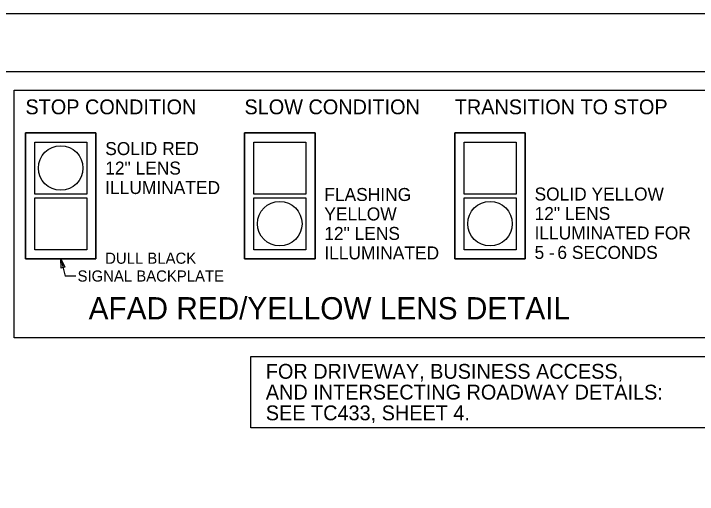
# Model space of a CAD drawing. Extents: x 99999.1 to 100095.7, y 99995 to 100010.7.
# Drawn here: x 100043.795 to 100047.479, y 100008.096 to 100010.687 of the extents above; entities that cross this region are included whole.
import ezdxf

# ---------------------------------------------------------------- set-up
doc = ezdxf.new("R2010")
doc.units = 0
for name, color, linetype in [('SH_GI_PlotLimits', 7, 'Continuous'), ('SH_GI_SheetBorder', 7, 'Continuous'), ('SH_TI_Tables', 7, 'Continuous'), ('TR_WZ_WorkZoneDetails', 7, 'Continuous')]:
    doc.layers.add(name, color=color, linetype=linetype)

msp = doc.modelspace()

# ---------------------------------------------------------------- linework, layer by layer
at = {"layer": 'SH_GI_PlotLimits'}
msp.add_lwpolyline([(100039.0625, 99999.6875), (100056.0625, 99999.6875), (100056.0625, 100010.6875), (100039.0625, 100010.6875)], close=True, dxfattribs=at)
at = {"layer": 'SH_GI_SheetBorder'}
msp.add_line((100040, 100010.375), (100055.75, 100010.375), dxfattribs=at)
at = {"layer": 'SH_TI_Tables'}
msp.add_lwpolyline([(100045.0739, 100008.839), (100047.5374, 100008.839), (100047.5374, 100008.455), (100045.0739, 100008.455)], close=True, dxfattribs=at)
at = {"layer": 'TR_WZ_WorkZoneDetails'}
for p in [(100044.0484, 100009.365), (100044.1292, 100009.273)]:
    msp.add_line(p, (100044.0723, 100009.273), dxfattribs=at)
for points in [[(100043.7984, 100010.275), (100047.5374, 100010.275), (100047.5374, 100008.939), (100043.7984, 100008.939)], [(100044.2384, 100010.045), (100043.8584, 100010.045), (100043.8584, 100009.365), (100044.2384, 100009.365)], [(100045.419, 100010.045), (100045.039, 100010.045), (100045.039, 100009.365), (100045.419, 100009.365)], [(100046.5523, 100010.045), (100046.1723, 100010.045), (100046.1723, 100009.365), (100046.5523, 100009.365)], [(100043.9084, 100009.995), (100044.1884, 100009.995), (100044.1884, 100009.715), (100043.9084, 100009.715)], [(100045.089, 100009.995), (100045.369, 100009.995), (100045.369, 100009.715), (100045.089, 100009.715)], [(100046.2223, 100009.995), (100046.5023, 100009.995), (100046.5023, 100009.715), (100046.2223, 100009.715)], [(100043.9084, 100009.695), (100044.1884, 100009.695), (100044.1884, 100009.415), (100043.9084, 100009.415)], [(100045.089, 100009.695), (100045.369, 100009.695), (100045.369, 100009.415), (100045.089, 100009.415)], [(100046.2223, 100009.695), (100046.5023, 100009.695), (100046.5023, 100009.415), (100046.2223, 100009.415)], [(100044.0484, 100009.365), (100044.07, 100009.3198), (100044.0601, 100009.3196), (100044.0514, 100009.315)]]:
    msp.add_lwpolyline(points, close=True, dxfattribs=at)
for points in [[(100043.8584, 100010.045), (100044.2384, 100010.045), (100044.2384, 100009.365), (100043.8584, 100009.365), (100043.8584, 100010.045)], [(100045.039, 100010.045), (100045.419, 100010.045), (100045.419, 100009.365), (100045.039, 100009.365), (100045.039, 100010.045)], [(100046.1723, 100010.045), (100046.5523, 100010.045), (100046.5523, 100009.365), (100046.1723, 100009.365), (100046.1723, 100010.045)], [(100043.9084, 100009.995), (100044.1884, 100009.995), (100044.1884, 100009.715), (100043.9084, 100009.715), (100043.9084, 100009.995)], [(100045.089, 100009.995), (100045.369, 100009.995), (100045.369, 100009.715), (100045.089, 100009.715), (100045.089, 100009.995)], [(100046.2223, 100009.995), (100046.5023, 100009.995), (100046.5023, 100009.715), (100046.2223, 100009.715), (100046.2223, 100009.995)], [(100043.9084, 100009.695), (100044.1884, 100009.695), (100044.1884, 100009.415), (100043.9084, 100009.415), (100043.9084, 100009.695)], [(100045.089, 100009.695), (100045.369, 100009.695), (100045.369, 100009.415), (100045.089, 100009.415), (100045.089, 100009.695)], [(100046.2223, 100009.695), (100046.5023, 100009.695), (100046.5023, 100009.415), (100046.2223, 100009.415), (100046.2223, 100009.695)]]:
    msp.add_lwpolyline(points, dxfattribs=at)
for centre in [(100044.0484, 100009.855), (100045.229, 100009.555), (100046.3623, 100009.555)]:
    msp.add_circle(centre, 0.12, dxfattribs=at)

# ---------------------------------------------------------------- texts
at = {"layer": 'SH_TI_Tables'}
for s, p in [('FOR DRIVEWAY, BUSINESS ACCESS,', (100045.1539, 100008.719)), ('AND INTERSECTING ROADWAY DETAILS:', (100045.1539, 100008.607)), ('SEE TC433, SHEET 4.', (100045.1539, 100008.495))]:
    msp.add_text(s, height=0.08, rotation=360, dxfattribs=at).set_placement(p)
at = {"layer": 'TR_WZ_WorkZoneDetails'}
for s, height, p in [('STOP CONDITION', 0.08, (100043.8584, 100010.145)), ('SLOW CONDITION', 0.08, (100045.039, 100010.145)), ('TRANSITION TO STOP', 0.08, (100046.1723, 100010.145)), ('SOLID RED', 0.07, (100044.2884, 100009.925)), ('12" LENS ', 0.07, (100044.2884, 100009.82)), ('ILLUMINATED', 0.07, (100044.2884, 100009.715)), ('FLASHING', 0.07, (100045.469, 100009.6775)), ('SOLID YELLOW', 0.07, (100046.6023, 100009.68)), ('YELLOW', 0.07, (100045.469, 100009.5725)), ('12" LENS ', 0.07, (100046.6023, 100009.575)), ('12" LENS ', 0.07, (100045.469, 100009.4675)), ('ILLUMINATED FOR', 0.07, (100046.6023, 100009.47)), ('ILLUMINATED', 0.07, (100045.469, 100009.3625)), ('5', 0.07, (100046.6023, 100009.365)), ('6 SECONDS', 0.07, (100046.7251, 100009.365)), ('DULL BLACK', 0.06, (100044.2881, 100009.339)), ('-', 0.07, (100046.6796, 100009.365)), ('SIGNAL BACKPLATE', 0.06, (100044.1392, 100009.243))]:
    msp.add_text(s, height=height, dxfattribs=at).set_placement(p)
msp.add_text('AFAD RED/YELLOW LENS DETAIL', height=0.12, rotation=360, dxfattribs=at).set_placement((100044.1989, 100009.039))

doc.saveas('drawing.dxf')
